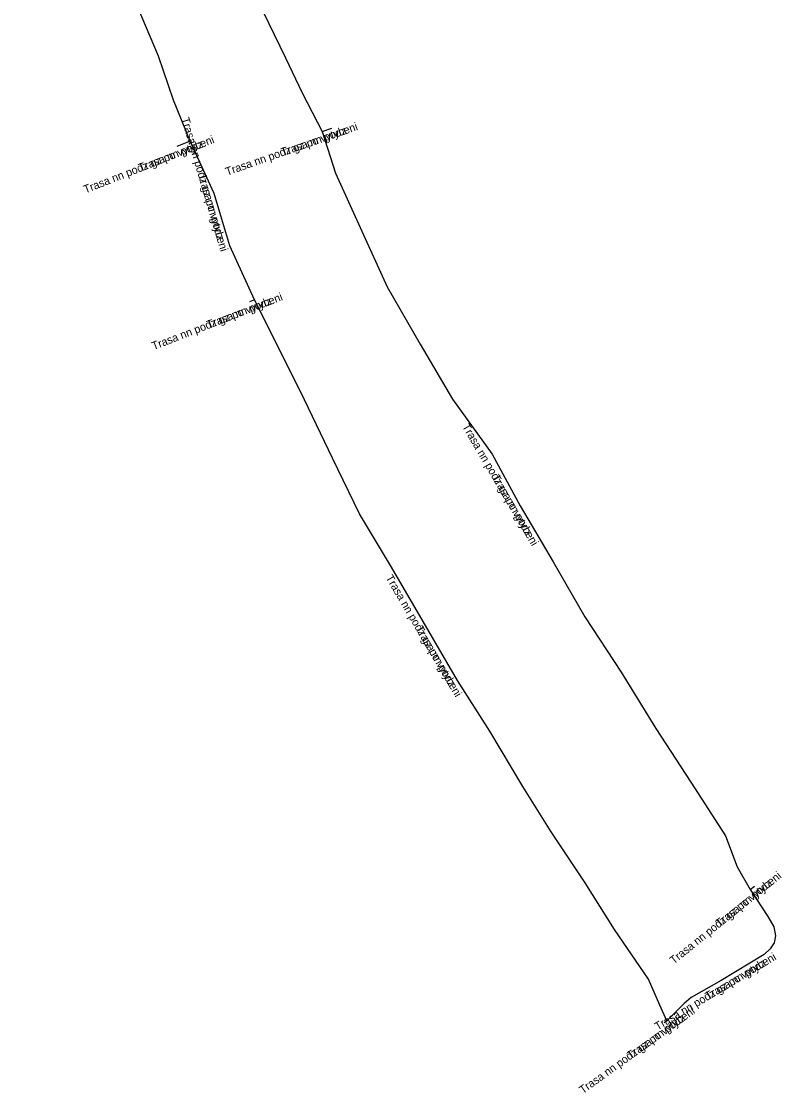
# Model space of a CAD drawing. Extents: x -712398 to -711995, y -1018801 to -1015851.
# Drawn here: x -712318.6 to -712271.1, y -1016115.2 to -1016048.3 of the extents above; entities that cross this region are included whole.
import ezdxf

# ---------------------------------------------------------------- set-up
doc = ezdxf.new("R2010")
doc.units = 0
doc.layers.add('Popiskový text - Ostatní atributy Trasy', color=7, linetype='Continuous')
doc.layers.add('Spojnice NN', color=7, linetype='Continuous')

msp = doc.modelspace()

# ---------------------------------------------------------------- linework, layer by layer
at = {"layer": 'Spojnice NN'}
for points in [[(-712308.07, -1016055.77), (-712309.12, -1016053.2), (-712310.04, -1016050.46), (-712311.61, -1016046.74), (-712312.12, -1016045.23), (-712314.84, -1016041.61), (-712315.79, -1016039.37), (-712317.12, -1016036.22), (-712318.61, -1016033.01)], [(-712308.07, -1016055.77), (-712309.12, -1016053.2), (-712310.04, -1016050.46), (-712311.61, -1016046.74), (-712312.12, -1016045.23), (-712314.84, -1016041.61), (-712315.79, -1016039.37), (-712317.12, -1016036.22), (-712318.61, -1016033.01)], [(-712308.98, -1016033.76), (-712308.17, -1016036.68), (-712306.7, -1016040.1), (-712305.18, -1016043.71), (-712303.53, -1016047.64), (-712302.12, -1016050.56), (-712301.08, -1016052.74), (-712299.83, -1016055.16)], [(-712308.98, -1016033.76), (-712308.17, -1016036.68), (-712306.7, -1016040.1), (-712305.18, -1016043.71), (-712303.53, -1016047.64), (-712302.12, -1016050.56), (-712301.08, -1016052.74), (-712299.83, -1016055.16)], [(-712299.83, -1016055.16), (-712299.23, -1016054.95)], [(-712299.83, -1016055.16), (-712299.23, -1016054.95)], [(-712299.83, -1016055.16), (-712298.99, -1016057.76), (-712297.44, -1016061.17), (-712295.77, -1016064.87), (-712293.7, -1016068.46), (-712291.68, -1016071.88), (-712289.21, -1016075.33), (-712287.45, -1016078.55), (-712285.4, -1016082.06), (-712283.41, -1016085.48), (-712281.15, -1016088.94), (-712278.98, -1016092.46), (-712276.8, -1016095.82), (-712274.62, -1016099.16), (-712273.91, -1016101.1), (-712273.08, -1016102.52)], [(-712299.83, -1016055.16), (-712298.99, -1016057.76), (-712297.44, -1016061.17), (-712295.77, -1016064.87), (-712293.7, -1016068.46), (-712291.68, -1016071.88), (-712289.21, -1016075.33), (-712287.45, -1016078.55), (-712285.4, -1016082.06), (-712283.41, -1016085.48), (-712281.15, -1016088.94), (-712278.98, -1016092.46), (-712276.8, -1016095.82), (-712274.62, -1016099.16), (-712273.91, -1016101.1), (-712273.08, -1016102.52)], [(-712308.07, -1016055.77), (-712308.91, -1016056.1)], [(-712308.07, -1016055.77), (-712308.91, -1016056.1)], [(-712304.06, -1016065.69), (-712305.6, -1016062.31), (-712306.09, -1016060.65), (-712306.58, -1016059.03), (-712308.07, -1016055.77)], [(-712304.06, -1016065.69), (-712305.6, -1016062.31), (-712306.09, -1016060.65), (-712306.58, -1016059.03), (-712308.07, -1016055.77)], [(-712304.06, -1016065.69), (-712304.37, -1016065.81)], [(-712304.06, -1016065.69), (-712304.37, -1016065.81)], [(-712278.29, -1016110.72), (-712278.74, -1016109.74), (-712279.44, -1016108.12), (-712281.57, -1016105.02), (-712283.4, -1016102.1), (-712285.51, -1016098.93), (-712287.28, -1016096.09), (-712289.36, -1016092.64), (-712291.37, -1016089.46), (-712293.52, -1016085.78), (-712295.49, -1016082.38), (-712297.5, -1016079.06), (-712299.18, -1016075.58), (-712300.93, -1016071.92), (-712302.54, -1016068.71), (-712304.06, -1016065.69)], [(-712278.29, -1016110.72), (-712278.74, -1016109.74), (-712279.44, -1016108.12), (-712281.57, -1016105.02), (-712283.4, -1016102.1), (-712285.51, -1016098.93), (-712287.28, -1016096.09), (-712289.36, -1016092.64), (-712291.37, -1016089.46), (-712293.52, -1016085.78), (-712295.49, -1016082.38), (-712297.5, -1016079.06), (-712299.18, -1016075.58), (-712300.93, -1016071.92), (-712302.54, -1016068.71), (-712304.06, -1016065.69)], [(-712273.08, -1016102.52), (-712272.82, -1016102.31)], [(-712273.08, -1016102.52), (-712272.82, -1016102.31)], [(-712273.08, -1016102.52), (-712271.98, -1016104.21), (-712271.62, -1016104.86), (-712271.5, -1016105.41), (-712271.58, -1016105.86), (-712271.83, -1016106.22), (-712272.21, -1016106.59), (-712274.91, -1016108.21), (-712276.78, -1016109.27), (-712277.21, -1016109.64), (-712277.75, -1016110.18), (-712278.29, -1016110.72)], [(-712273.08, -1016102.52), (-712271.98, -1016104.21), (-712271.62, -1016104.86), (-712271.5, -1016105.41), (-712271.58, -1016105.86), (-712271.83, -1016106.22), (-712272.21, -1016106.59), (-712274.91, -1016108.21), (-712276.78, -1016109.27), (-712277.21, -1016109.64), (-712277.75, -1016110.18), (-712278.29, -1016110.72)], [(-712278.29, -1016110.72), (-712278.47, -1016110.85)], [(-712278.29, -1016110.72), (-712278.47, -1016110.85)]]:
    msp.add_lwpolyline(points, dxfattribs=at)

# ---------------------------------------------------------------- texts
at = {"layer": 'Popiskový text - Ostatní atributy Trasy'}
for s, rotation, p in [('Trasa nn podz gz po vytyceni', 286.44558, (-712308.624, -1016054.362)), ('Trasa nn podz gz po vytyceni', 19.29005, (-712305.764, -1016057.926)), ('Trasa nn podz', 19.29005, (-712302.286, -1016056.709)), ('Trasa nn podz gz po vytyceni', 21.44774, (-712314.612, -1016059.038)), ('Trasa nn podz', 21.44774, (-712311.182, -1016057.691)), ('Trasa nn podz', 286.44558, (-712307.581, -1016057.896)), ('Trasa nn podz gz po vytyceni', 21.16126, (-712310.353, -1016068.823)), ('Trasa nn podz', 21.16126, (-712306.916, -1016067.492)), ('Trasa nn podz gz po vytyceni', 300.28688, (-712291.097, -1016073.594)), ('Trasa nn podz', 300.28688, (-712289.238, -1016076.776)), ('Trasa nn podz gz po vytyceni', 300.29514, (-712295.875, -1016083.038)), ('Trasa nn podz', 300.29514, (-712294.016, -1016086.219)), ('Trasa nn podz gz po vytyceni', 38.92754, (-712277.857, -1016107.214)), ('Trasa nn podz', 38.92754, (-712274.991, -1016104.898)), ('Trasa nn podz gz po vytyceni', 30.96376, (-712278.868, -1016111.343)), ('Trasa nn podz', 30.96376, (-712275.708, -1016109.447)), ('Trasa nn podz gz po vytyceni', 35.83765, (-712283.539, -1016115.312)), ('Trasa nn podz', 35.83765, (-712280.551, -1016113.155))]:
    msp.add_text(s, height=0.5, rotation=rotation, dxfattribs=at).set_placement(p)

doc.saveas('drawing.dxf')
